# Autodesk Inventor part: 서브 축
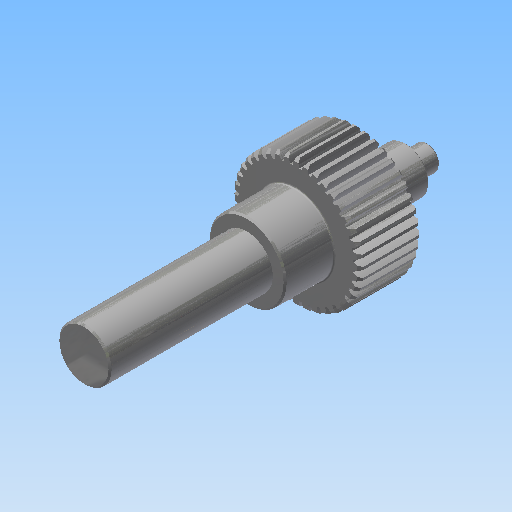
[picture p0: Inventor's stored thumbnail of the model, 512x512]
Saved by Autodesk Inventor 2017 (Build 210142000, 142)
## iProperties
Created: 2016-02
Part Number: 서브 축
Material: 강철, 연강
Document SubType Name: Modeling
Designer: mdu
Categories: <?xml version="1.0" encoding="UTF-16"?> <MemberInstance><Categories><FamilyTemplate><FamilyTemplateParameter ValueType="xs:double" Id="1" ObjectReferenceKey="da
Density: 7.86 g/cm^3
Appearance: 강철
CustomPartVersion: 1
Author: mdu
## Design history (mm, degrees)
sketch "Sketch1"
  geometry: C1 r 21 at (0, 0)
  constraints: 1 centre point
  dimensions: "d0" = 42 diameter of C1 (= da_da)
extrude "Extrusion1" new body sketch "Sketch1" distance "d1" = 20 (= da_b); taper "d2" = 0 deg
workplane "Work Plane2"
feature "피치 지름" dims "d4" = 10, "d5" = 0
workplane "Work Plane8"
workplane "Work Plane9"
chamfer "모따기1" distance "d49" = 1; stored, may be unused: second distance "d50" = 2, angle "d51" = 45 deg
sketch "스케치3"
  geometry: C1 r 12.5 at (0, 0); 1 further point
  constraints: 1 centre point, 1 coincident
  dimensions: "d52" = 25 diameter of C1
extrude "돌출2" join sketch "스케치3" distance "d53" = 16; taper "d54" = 0 deg
sketch "스케치4"
  geometry: C1 r 8.5 at (0, 0); 1 further point
  constraints: 1 centre point, 1 coincident
  dimensions: "d55" = 17 diameter of C1
extrude "돌출3" join sketch "스케치4" distance "d56" = 53; taper "d57" = 0 deg
sketch "스케치5"
  geometry: C1 r 7.5 at (0, 0); 1 further point
  constraints: 1 centre point, 1 coincident
  dimensions: "d62" = 15 diameter of C1
extrude "돌출4" join sketch "스케치5" distance "d63" = 16; taper "d64" = 0 deg
sketch "스케치6"
  geometry: C1 r 4 at (0, 0); 1 further point
  constraints: 1 centre point, 1 coincident
  dimensions: "d65" = 8 diameter of C1
extrude "돌출5" join sketch "스케치6" distance "d66" = 7; taper "d67" = 0 deg
chamfer "모따기2" distance "d58" = 0.5; stored, may be unused: second distance "d59" = 2, angle "d60" = 45 deg
fillet "모깎기1" dims "d61" = 0.5
feature "스퍼 기어" dims "da_b" = 20, "da_d" = 40, "da_aw" = 31, "da_da" = 42, "da_df" = 37.5, "da_dw" = 40, angle "da_beta" = 0 deg, "da_lefttooth" = 0, "da_righttooth" = 0
body "Solid1"
sketch "Sketch2"
  geometry: C1 r 21 at (0, 0) reference; C2 r 20 at (0, 0)
  constraints: 1 centre point, 1 coincident
  dimensions: "d3" = 40 diameter of C2 (= da_dw)
body "Srf1"
other parameters: "d16" = 31 (= da_aw), "d17" = 0, "d34" = 4.5 deg (computed from da_z), "d39" = 0, "d41" = 0, "d43" = 31 (= da_aw), "d46" = 31 (= da_aw), "d47" = 0, "d48" = 0
